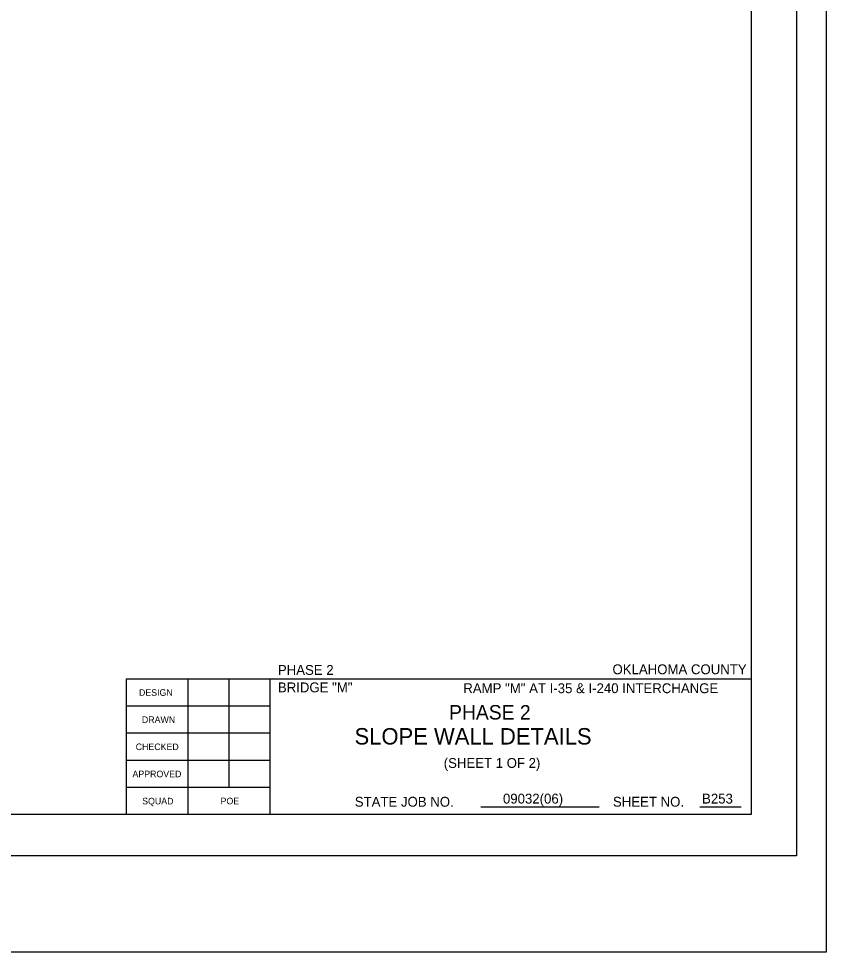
# Model space of a CAD drawing. Extents: x 570 to 2153298, y 726 to 139926.
# Drawn here: x 2153219.5 to 2153298.1, y 139657.7 to 139748.6 of the extents above; entities that cross this region are included whole.
import ezdxf

# ---------------------------------------------------------------- set-up
doc = ezdxf.new("R2010")
doc.units = 0
for name, color, linetype in [('SHT_Plot_Shape_Full', 7, 'Continuous'), ('SHT_Plot_Shape_Half', 7, 'Continuous'), ('SHT_Sheet_Border', 7, 'Continuous'), ('SHT_Standard_Sheet_Lines', 7, 'Continuous'), ('SHT_Standard_Sheet_Txt', 7, 'Continuous'), ('T', 7, 'Continuous'), ('T-Title', 7, 'Continuous')]:
    doc.layers.add(name, color=color, linetype=linetype)

msp = doc.modelspace()

# ---------------------------------------------------------------- linework, layer by layer
at = {"layer": 'SHT_Plot_Shape_Full'}
msp.add_lwpolyline([(2153010.09, 139849.742), (2153298.09, 139849.742), (2153298.09, 139657.742), (2153010.09, 139657.742)], close=True, dxfattribs=at)
at = {"layer": 'SHT_Plot_Shape_Half'}
msp.add_lwpolyline([(2153023.19, 139843.142), (2153295.19, 139843.142), (2153295.19, 139667.142), (2153023.19, 139667.142)], close=True, dxfattribs=at)
at = {"layer": 'SHT_Sheet_Border'}
for p, q in [((2153229.99, 139671.142), (2153229.99, 139684.342)), ((2153229.99, 139684.342), (2153290.79, 139684.342)), ((2153243.99, 139671.142), (2153243.99, 139684.349)), ((2153243.99, 139671.142), (2153243.99, 139684.349))]:
    msp.add_line(p, q, dxfattribs=at)
msp.add_lwpolyline([(2153290.79, 139671.142), (2153038.79, 139671.142), (2153038.79, 139839.142), (2153290.79, 139839.142)], close=True, dxfattribs=at)
at = {"layer": 'SHT_Standard_Sheet_Lines'}
for p, q in [((2153235.99, 139671.142), (2153235.99, 139684.349)), ((2153239.99, 139673.783), (2153239.99, 139684.349)), ((2153264.476, 139671.911), (2153275.999, 139671.912)), ((2153264.476, 139671.911), (2153275.999, 139671.912)), ((2153285.794, 139671.911), (2153289.814, 139671.912)), ((2153285.794, 139671.911), (2153289.814, 139671.912))]:
    msp.add_line(p, q, dxfattribs=at)
for points in [[(2153243.99, 139681.702), (2153229.99, 139681.702)], [(2153243.99, 139679.062), (2153229.99, 139679.062)], [(2153243.99, 139676.422), (2153229.99, 139676.422)], [(2153243.99, 139673.782), (2153229.99, 139673.782)]]:
    msp.add_lwpolyline(points, dxfattribs=at)

# ---------------------------------------------------------------- texts
at = {"layer": 'Defpoints'}
msp.add_text('PHASE 2', height=1.4062, dxfattribs=at).set_placement((2153261.379, 139680.395))
at = {"layer": 'SHT_Standard_Sheet_Txt'}
for s, height, p in [('DESIGN', 0.64, (2153231.208, 139682.702)), ('DRAWN', 0.64, (2153231.494, 139680.061)), ('CHECKED', 0.64, (2153230.893, 139677.42)), ('APPROVED', 0.64, (2153230.579, 139674.778)), ('SQUAD', 0.64, (2153231.522, 139672.137)), ('POE', 0.64, (2153239.151, 139672.142)), ('STATE JOB NO.', 0.96, (2153252.207, 139671.911)), ('STATE JOB NO.', 0.95999, (2153252.207, 139671.911)), ('SHEET NO. ', 0.96, (2153277.328, 139671.912)), ('SHEET NO. ', 0.96, (2153277.328, 139671.912))]:
    msp.add_text(s, height=height, dxfattribs=at).set_placement(p)
at = {"layer": 'T'}
for s, height, p in [('PHASE 2', 0.96, (2153244.726, 139684.736)), ('OKLAHOMA COUNTY', 0.95999, (2153277.284, 139684.8)), ('BRIDGE "M"', 0.96, (2153244.726, 139683.042)), ('RAMP "M" AT I-35 & I-240 INTERCHANGE', 0.95999, (2153262.769, 139682.96)), ('(SHEET 1 OF 2)', 0.95833, (2153260.864, 139675.687)), ('09032(06)', 0.96, (2153266.626, 139672.217)), ('B253', 0.96, (2153285.999, 139672.217))]:
    msp.add_text(s, height=height, dxfattribs=at).set_placement(p)
at = {"layer": 'T-Title'}
msp.add_text('SLOPE WALL DETAILS', height=1.59999, dxfattribs=at).set_placement((2153252.184, 139677.963))

doc.saveas('drawing.dxf')
